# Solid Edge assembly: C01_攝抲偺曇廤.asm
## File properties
Author: edge
Template: Normal.asm
Last saved by: edge
Revision: 19
Application: Solid Edge
文書内容のタイプ: 1
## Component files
C01_A.par
C01_E.par
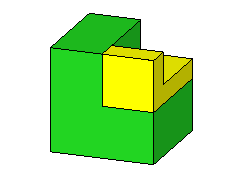
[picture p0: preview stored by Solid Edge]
